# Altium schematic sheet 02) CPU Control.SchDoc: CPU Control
size A3; SheetNumber: 2; SheetTotal: 3
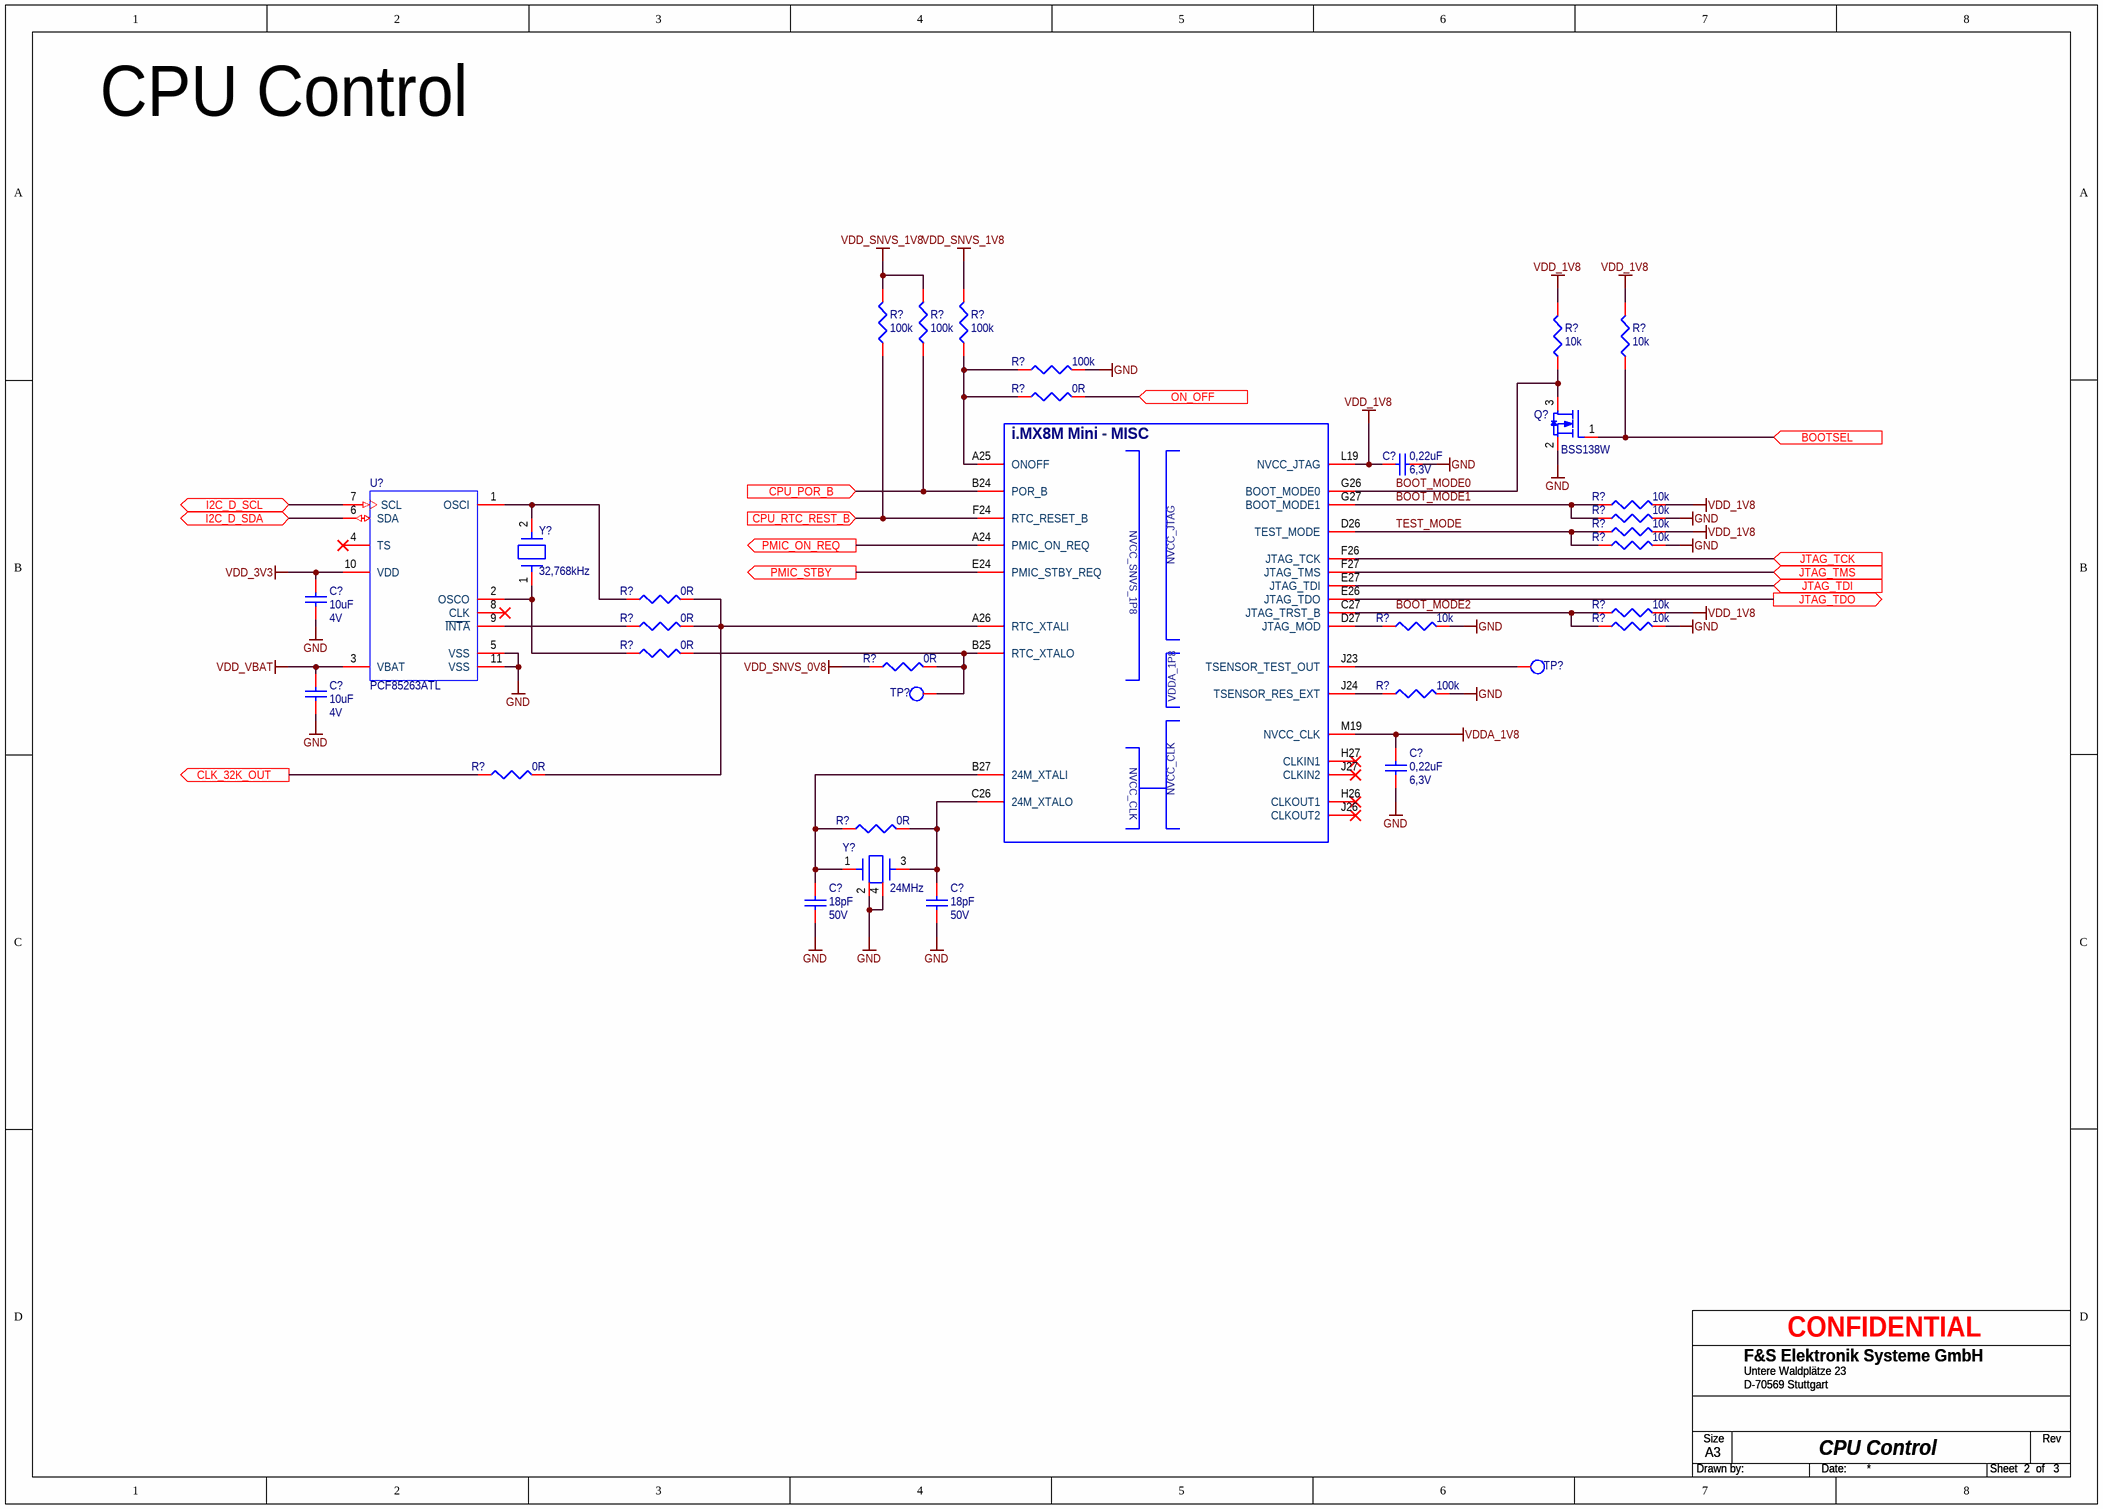
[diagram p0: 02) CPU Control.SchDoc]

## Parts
(Parts that share a designator on the sheet are numbered #1, #2 ... from top to bottom, then left to right.)
C?#1  0,22uF  Voltage: 6,3V  [C0201]
C?#2  10uF  Voltage: 4V  [C0402]
C?#3  10uF  Voltage: 4V  [C0402]
C?#4  0,22uF  Voltage: 6,3V  [C0201]
C?#5  18pF  Voltage: 50V  [C0201]
C?#6  18pF  Voltage: 50V  [C0201]
Q?  BSS138W  [SOT323 (SC70)]
R?#1  100k  [R0402]
R?#2  100k  [R0402]
R?#3  100k  [R0402]
R?#4  10k  [R0402]
R?#5  10k  [R0402]
R?#6  100k  [R0402]
R?#7  0R  [R0402]
R?#8  10k  [R0402]
R?#9  10k  [R0402]
R?#10  10k  [R0402]
R?#11  10k  [R0402]
R?#12  0R  [R0402]
R?#13  10k  [R0402]
R?#14  0R  [R0402]
R?#15  10k  [R0402]
R?#16  10k  [R0402]
R?#17  0R  [R0402]
R?#18  0R  [R0402]
R?#19  100k  [R0402]
R?#20  0R  [R0402]
R?#21  0R  [R0402]
TP?#1  TESTPOINT  [TP30SR34SMD]  (value not drawn)
TP?#2  TESTPOINT  [TP30SR34SMD]  (value not drawn)
U?#1  MIMX8MM_BGA486P  [FCBGA_14x14]  (value not drawn)  (part L of 14)
U?#2  PCF85263ATL  [DFN2626-10]
Y?#1  32,768kHz  [XTALSD-2-302X105MM]
Y?#2  24MHz  [XTALD-4-302X205M]

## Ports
BOOTSEL (in), CLK_32K_OUT (out), CPU_POR_B (in), CPU_RTC_REST_B (in), I2C_D_SCL (bidir), I2C_D_SDA (bidir), JTAG_TCK (in), JTAG_TDI (in), JTAG_TDO (out), JTAG_TMS (in), ON_OFF (in), PMIC_ON_REQ (out), PMIC_STBY (out)

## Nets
GND: C?#1.1 C?#2.1 C?#3.1 C?#4.1 C?#5.1 C?#6.1 Q?.2 R?#6.2 R?#9.2 R?#11.2 R?#15.2 R?#16.2 R?#19.2 U?#2.5(VSS) U?#2.11(VSS) Y?#2.2(Y4) Y?#2.4(Y3)
VDD_1V8: C?#1.2 R?#4.2 R?#5.2 R?#8.2 R?#10.2 R?#13.2 U?#1.L19(NVCC_JTAG)
VDD_3V3: C?#2.2 U?#2.10(VDD)
VDD_SNVS_0V8: R?#18.1
VDD_SNVS_1V8: R?#1.2 R?#2.2 R?#3.2
VDD_VBAT: C?#3.2 U?#2.3(VBAT)
VDDA_1V8: C?#4.2 U?#1.M19(NVCC_CLK)
BOOT_MODE0: Q?.3 R?#4.1 U?#1.G26(BOOT_MODE0)
BOOT_MODE1: R?#8.1 R?#9.1 U?#1.G27(BOOT_MODE1)
BOOT_MODE2: R?#13.1 R?#16.1 U?#1.C27(JTAG_TRST_B)
BOOTSEL: Q?.1 R?#5.1 ; port BOOTSEL
CLK_32K_OUT: R?#20.1 ; port CLK_32K_OUT
CPU_POR_B: R?#2.1 U?#1.B24(POR_B) ; port CPU_POR_B
CPU_RTC_REST_B: R?#1.1 U?#1.F24(RTC_RESET_B) ; port CPU_RTC_REST_B
I2C_D_SCL: U?#2.7(SCL) ; port I2C_D_SCL
I2C_D_SDA: U?#2.6(SDA) ; port I2C_D_SDA
JTAG_TCK: U?#1.F26(JTAG_TCK) ; port JTAG_TCK
JTAG_TDI: U?#1.E27(JTAG_TDI) ; port JTAG_TDI
JTAG_TDO: U?#1.E26(JTAG_TDO) ; port JTAG_TDO
JTAG_TMS: U?#1.F27(JTAG_TMS) ; port JTAG_TMS
ON_OFF: R?#7.2 ; port ON_OFF
PMIC_ON_REQ: U?#1.A24(PMIC_ON_REQ) ; port PMIC_ON_REQ
PMIC_STBY: U?#1.E24(PMIC_STBY_REQ) ; port PMIC_STBY
TEST_MODE: R?#10.1 R?#11.1 U?#1.D26(TEST_MODE)
NetC?#5_2: C?#5.2 R?#21.1 U?#1.B27(24M_XTALI) Y?#2.1(Y2)
NetC?#6_2: C?#6.2 R?#21.2 U?#1.C26(24M_XTALO) Y?#2.3(Y1)
NetR?#3_1: R?#3.1 R?#6.1 R?#7.1 U?#1.A25(ONOFF)
NetR?#12_1: R?#12.1 U?#2.1(OSCI) Y?#1.2(Y1)
NetR?#12_2: R?#12.2 R?#14.2 R?#20.2 U?#1.A26(RTC_XTALI)
NetR?#14_1: R?#14.1 U?#2.9(~{INTA})
NetR?#15_1: R?#15.1 U?#1.D27(JTAG_MOD)
NetR?#17_1: R?#17.1 U?#2.2(OSCO) Y?#1.1(Y2)
NetR?#17_2: R?#17.2 R?#18.2 TP?#2.1(TP) U?#1.B25(RTC_XTALO)
NetR?#19_1: R?#19.1 U?#1.J24(TSENSOR_RES_EXT)
NetTP?#1_1: TP?#1.1(TP) U?#1.J23(TSENSOR_TEST_OUT)

Not connected (* = marked no-connect by the designer): U?#1 H26(CLKOUT1)* H27(CLKIN1)* J26(CLKOUT2)* J27(CLKIN2)*; U?#2 4(TS)* 8(CLK)*

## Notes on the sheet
- CPU Control

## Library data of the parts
C?#1 C?#4 = 365: 0,22uF  20%  6,3V  X5R  0201; ID: 365; Class: Capacitor Ceramic; FS-EDV-Nummer: B.CKV.118; Tolerance: 20
C?#2 C?#3 = 394: 10uF  20%  4V  X5R  0402; ID: 394; Class: Capacitor Ceramic; FS-EDV-Nummer: B.CKV.77; Tolerance: 20
C?#5 C?#6 = 361: 18pF  2%  50V  C0G/NP0  0201; ID: 361; Class: Capacitor Ceramic; FS-EDV-Nummer: B.CKV.105; Tolerance: 2
Q? = 2689: BSS138W SOT323(SC-70) N-Kanal; ID: 2689; Class: MOSFET; FS-EDV-Nummer: B.TPMFN.10
R?#1-R?#3 R?#6 R?#19 = 177: 100k 1/16W 1% SMD 0402; ID: 177; FS-EDV-Nummer: B.R100K.3; Tolerance: 1
R?#4 R?#5 R?#8-R?#11 R?#13 R?#15 R?#16 = 170: 10k 1/16W 1% SMD 0402; ID: 170; FS-EDV-Nummer: B.R10K.3; Tolerance: 1
R?#7 R?#12 R?#14 R?#17 R?#18 R?#20 R?#21 = 173: 0R 1/16W max 5% SMD 0402; ID: 173; FS-EDV-Nummer: B.R0R0.1; Tolerance: 5
U?#1 = MIMX8MM_BGA486P: CLASS: IC; SPLIT_INST: TRUE
U?#2 = PCF85263: Real-Time Clock / Calendar, 1.8 to 5.5 V, -40 to 85 degC, 10-Pin DFN2626, RoHS, Tape and Reel; Manufacturer: NXP; Time Format: HH:MM:SS; Operating Supply Voltage (Max): 5.5V; Bus Type: Serial(2-Wire,I2C); Date Format: DW:DM:M:Y; Operating Supply Voltage (Typ): 2.5/3.3/5V; Operating Supply Voltage (Min): 1.8V; I2C-Address: 0x51
Y?#1 = 2777: 32,768kHz SMD FC-135; Part Number: FC135-32; ID: 2777; Class: Crystal; FS-EDV-Nummer: B.Q.18; Tolerance: 20ppm
Y?#2 = 2757: 24MHz 12pF 3.2x2.5 SMD; Part Number: Q22FA2380038014; ID: 2757; Class: Crystal; FS-EDV-Nummer: B.Q.28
